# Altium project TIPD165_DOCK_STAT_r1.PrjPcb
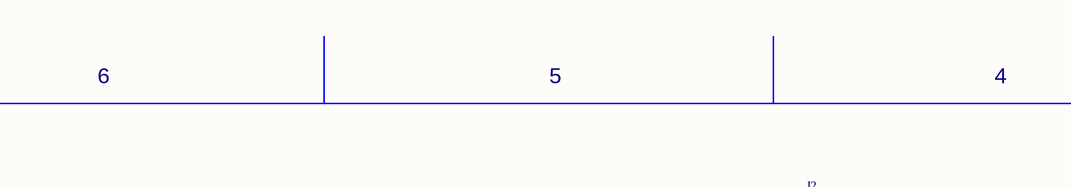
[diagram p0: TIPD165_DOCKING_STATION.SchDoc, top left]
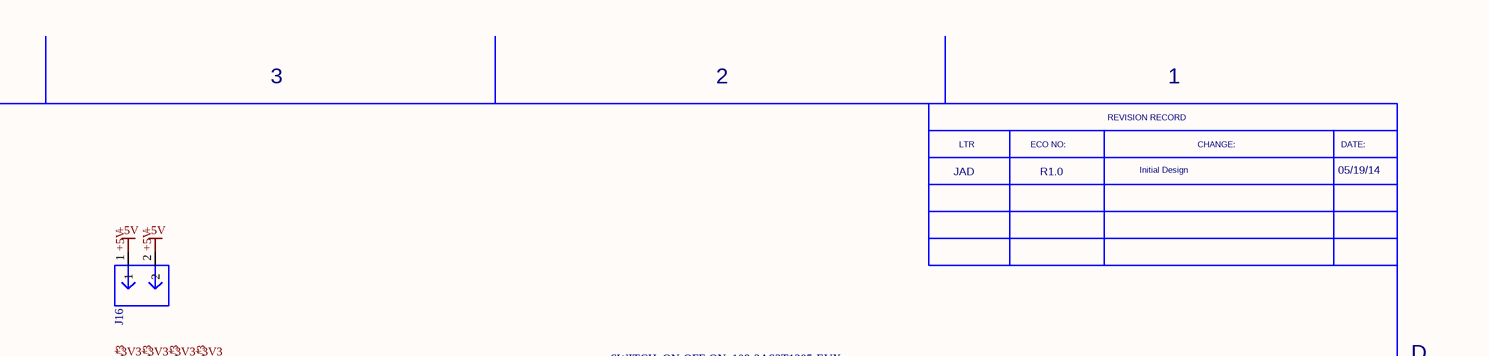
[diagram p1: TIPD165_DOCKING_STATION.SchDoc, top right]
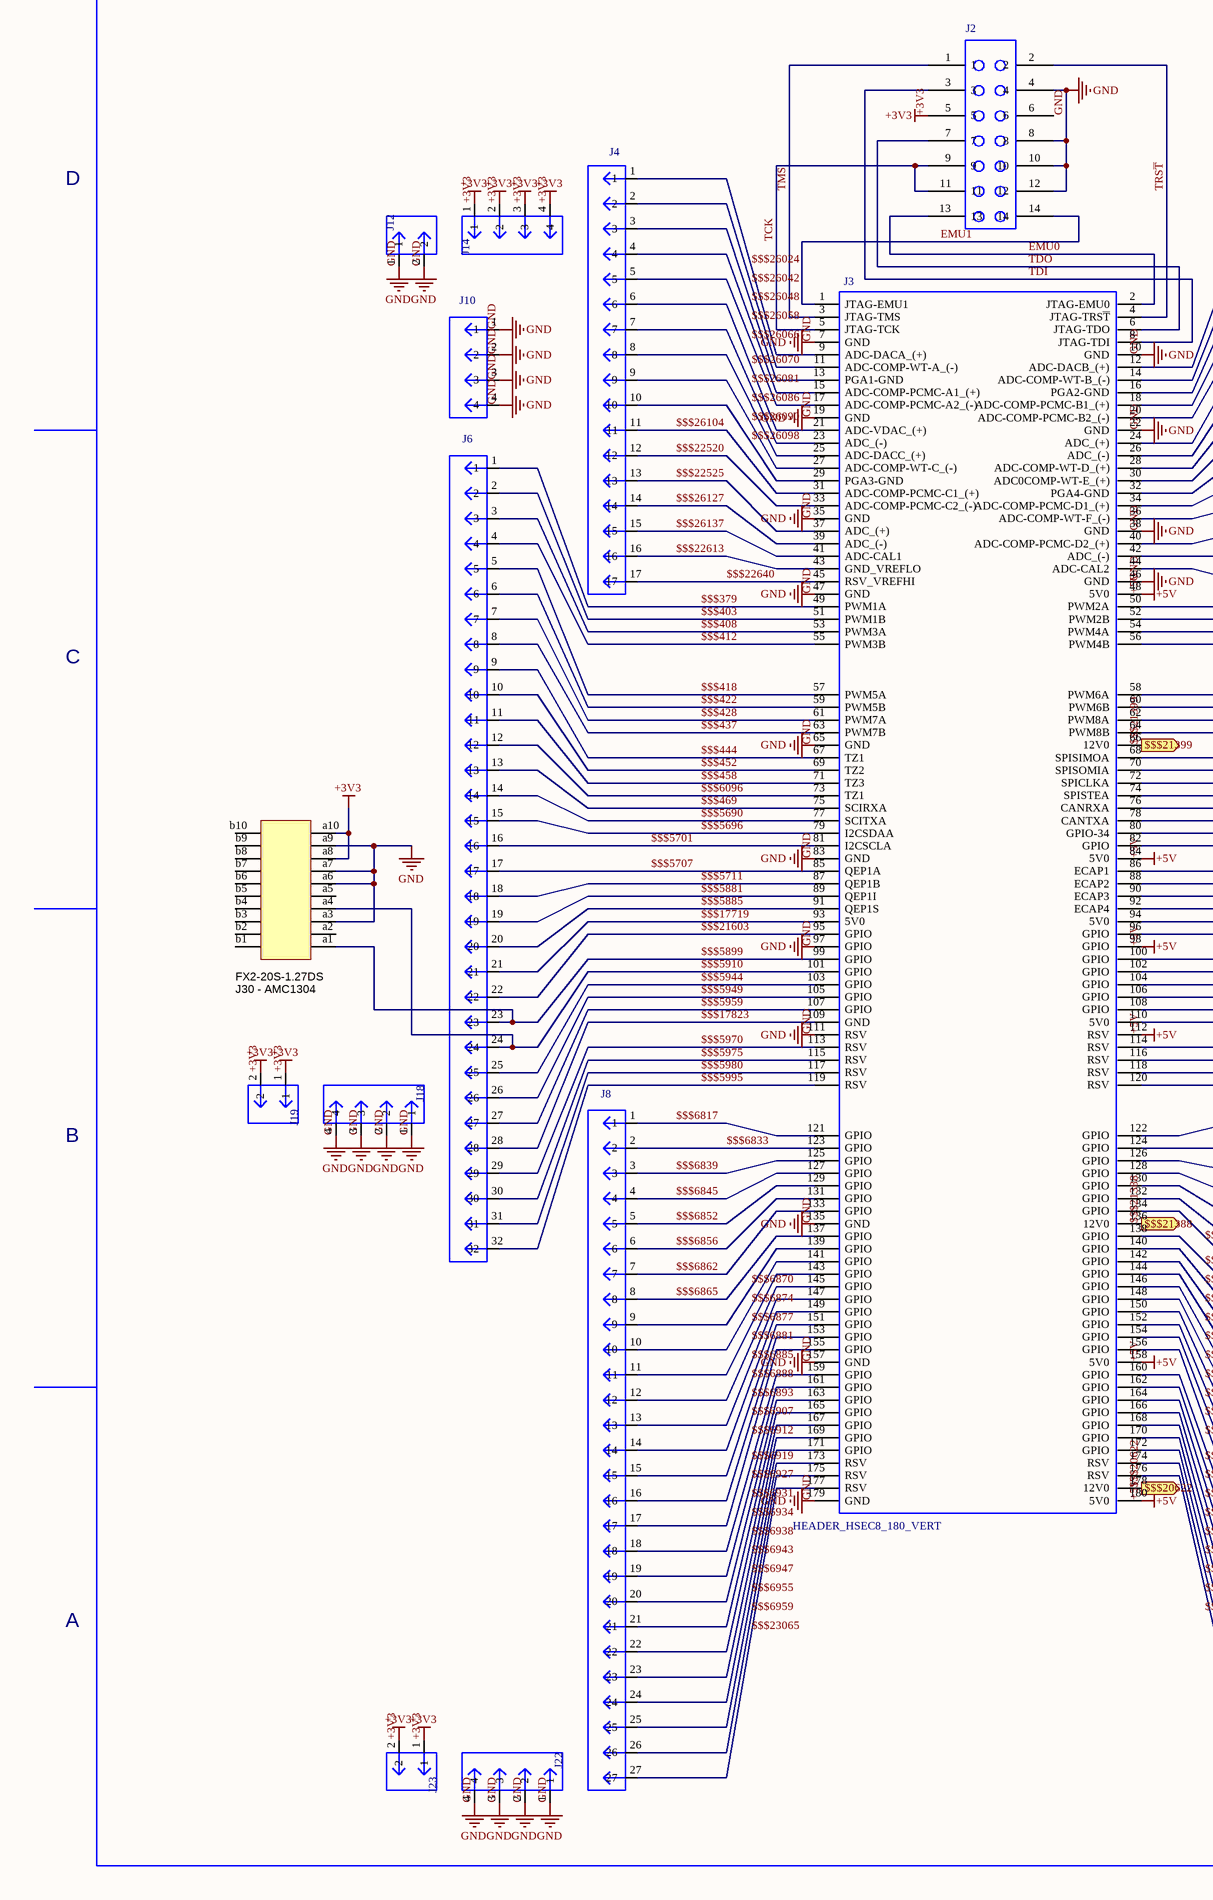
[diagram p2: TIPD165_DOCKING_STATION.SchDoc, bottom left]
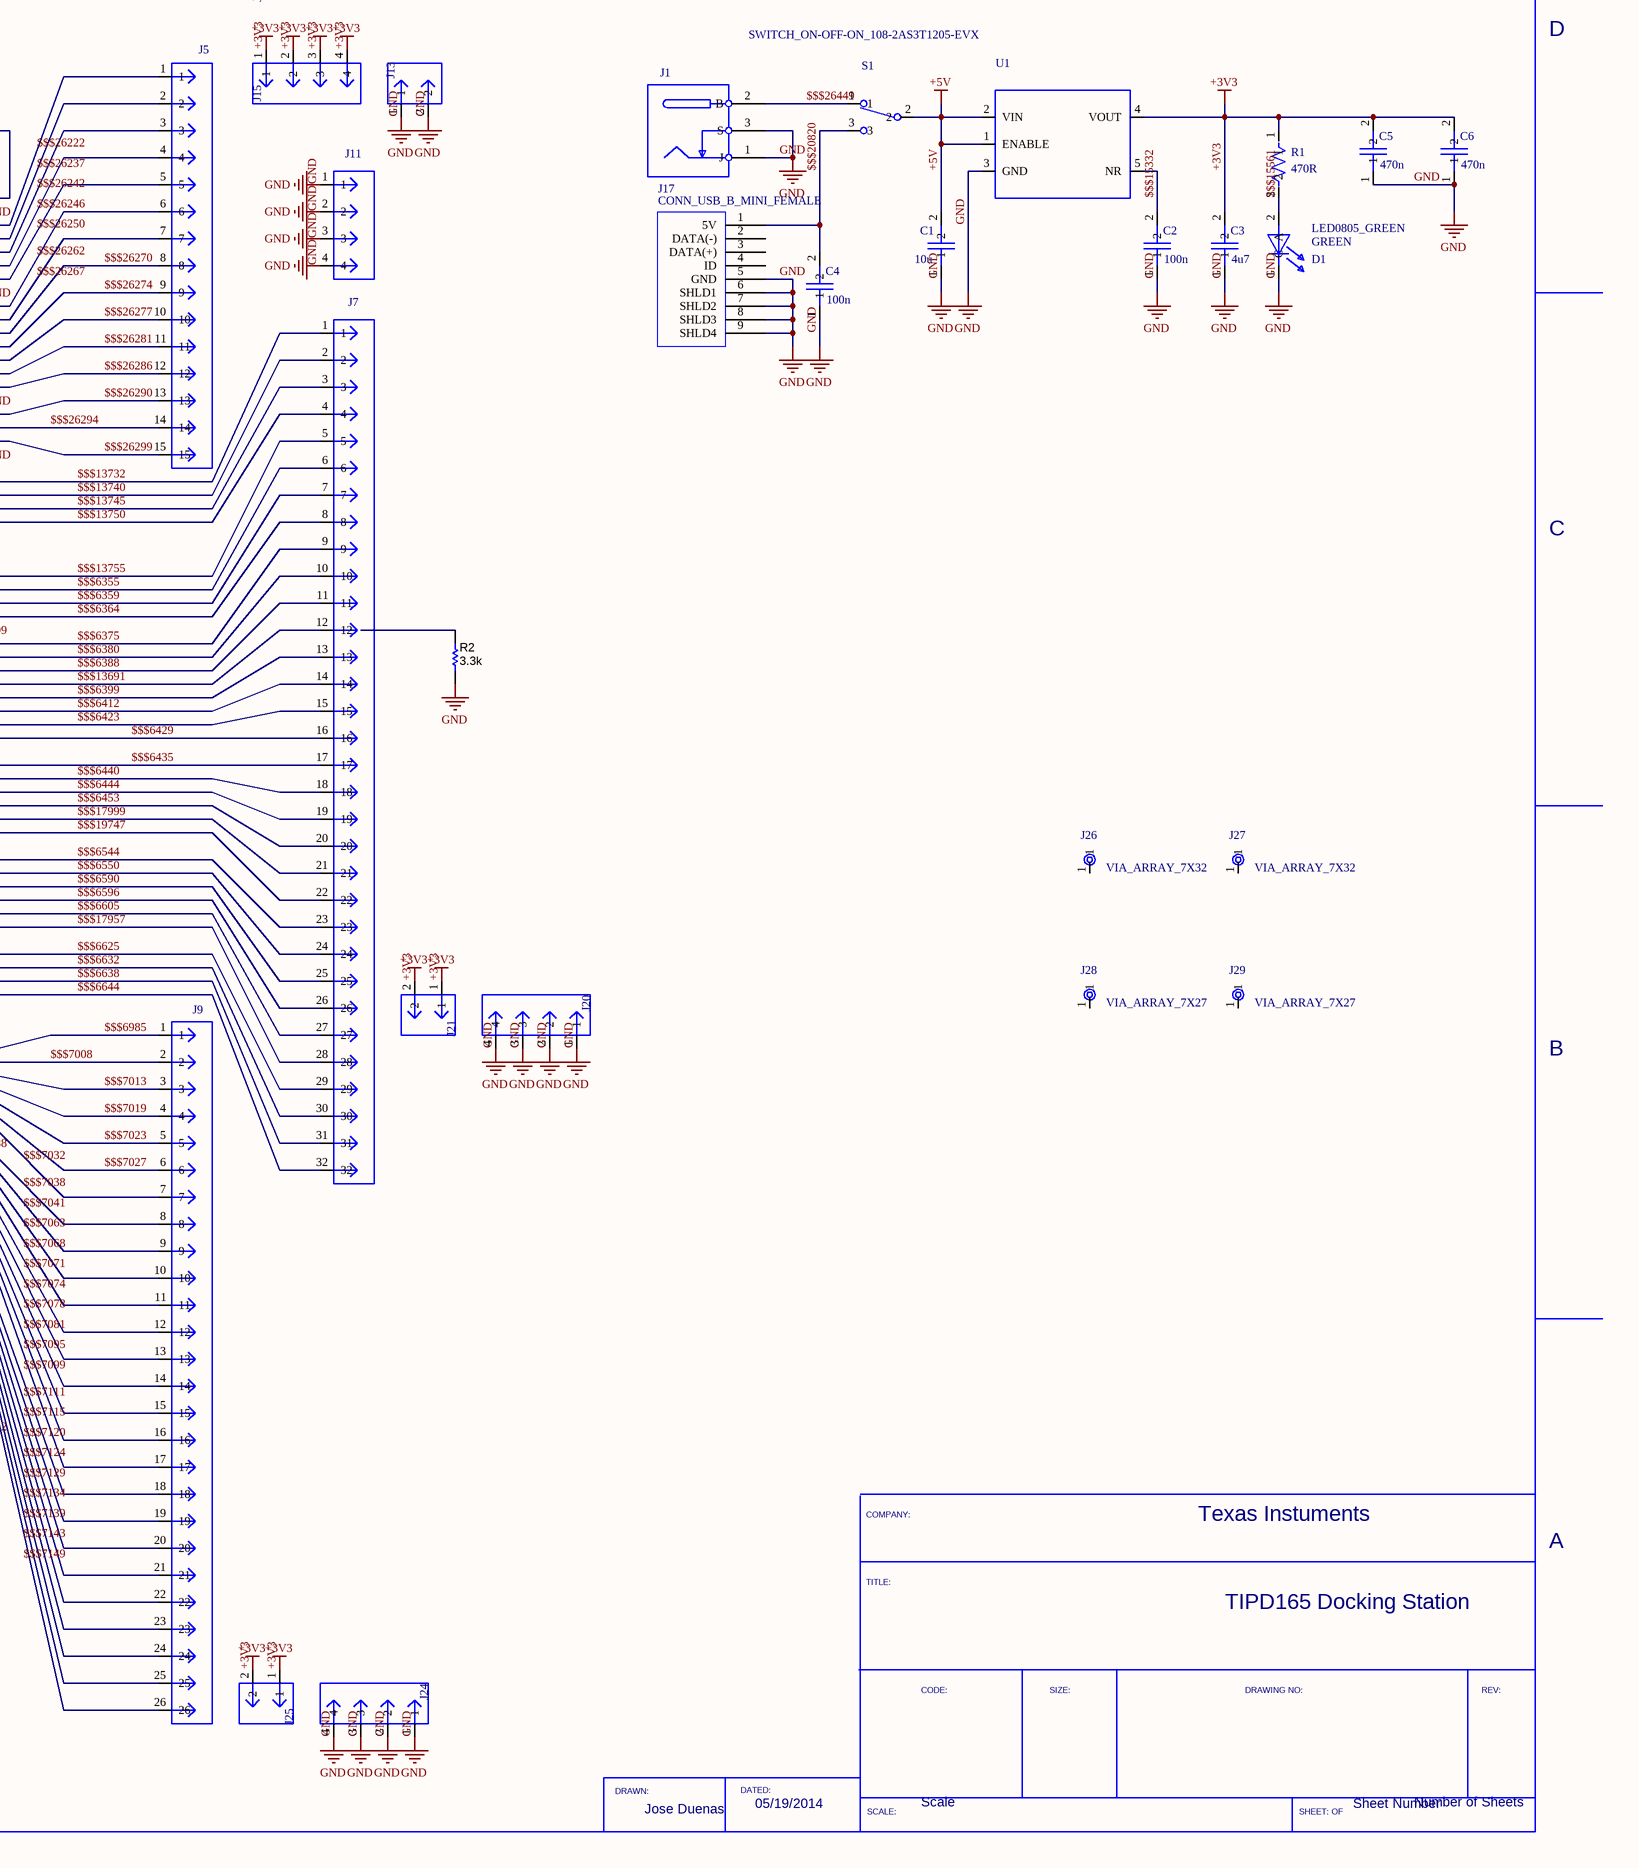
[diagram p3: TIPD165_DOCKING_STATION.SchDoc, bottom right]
1 sheet, 41 parts. Net scope: flat (ports and power ports of the same name join across sheets).
Board file: TIPD165_DOCK_STAT_r1.PcbDoc

## Sheet TIPD165_DOCKING_STATION.SchDoc: controlCARD Docking Station
size 558 x 431 mm; CompanyName: Texas Instruments Inc.; DrawnBy: SBL; Revision: 4.0; Drawn Date: 6/7/2012

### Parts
C1  value 10u  (hidden comment: C0805_6V3_X5R)
C2  value 100n  (hidden comment: C0805_6V3_X5R)
C3  value 4u7  (hidden comment: C0805_6V3_X5R)
C4  value 100n  (hidden comment: C0805_6V3_X5R)
C5  value 470n  (hidden comment: C0805_6V3_X5R)
C6  value 470n  (hidden comment: C0805_6V3_X5R)
D1  LED0805_GREEN  value GREEN
J1  CONN_PWR_JACK_2.5ID_5.5OD  (value not drawn)
J2  HEADER_7X2_100  (value not drawn)
J3  HEADER_HSEC8_180_VERT
J4  HEADER_1X17_100  (value not drawn)
J5  HEADER_1X15_100  (value not drawn)
J6  HEADER_1X32_100  (value not drawn)
J7  HEADER_1X32_100  (value not drawn)
J8  HEADER_1X27_100  (value not drawn)
J9  HEADER_1X26_100  (value not drawn)
J10  HEADER_1X4_100  (value not drawn)
J11  HEADER_1X4_100  (value not drawn)
J12  HEADER_1X2_100  (value not drawn)
J13  HEADER_1X2_100  (value not drawn)
J14  HEADER_1X4_100  (value not drawn)
J15  HEADER_1X4_100  (value not drawn)
J16  HEADER_1X2_100  (value not drawn)
J17  CONN_USB_B_MINI_FEMALE
J18  HEADER_1X4_100  (value not drawn)
J19  HEADER_1X2_100  (value not drawn)
J20  HEADER_1X4_100  (value not drawn)
J21  HEADER_1X2_100  (value not drawn)
J22  HEADER_1X4_100  (value not drawn)
J23  HEADER_1X2_100  (value not drawn)
J24  HEADER_1X4_100  (value not drawn)
J25  HEADER_1X2_100  (value not drawn)
J26  VIA_ARRAY_7X32
J27  VIA_ARRAY_7X32
J28  VIA_ARRAY_7X27
J29  VIA_ARRAY_7X27
J30_-_AMC1304  FX2-20S-1.27DS  [FX2_20P_1p27_DS_head_good]
R1  value 470R  (hidden comment: R0805_5%)
R2  ValueDisplayed: 3.3k  [0805_HV]  (hidden comment: ERJ-6GEYJ332V)
S1  SWITCH_ON-OFF-ON_108-2AS3T1205-EVX
U1  IC_LDO_TPS79533DCQ  (value not drawn)

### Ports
$$$20622, $$$21388, $$$21399

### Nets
+3V3: C3.2 C5.2 C6.2 J2.5 J14.1 J14.2 J14.3 J14.4 J15.1 J15.2 J15.3 J15.4 J19.1 J19.2 J21.1 J21.2 J23.1 J23.2 J25.1 J25.2 J30_-_AMC1304.a8 J30_-_AMC1304.a10 R1.1 U1.4(VOUT)
+5V: C1.2 J3.48(5V0) J3.84(5V0) J3.98(GPIO) J3.112(RSV) J3.158(5V0) J3.180(5V0) J16.1 J16.2 S1.2 U1.1(ENABLE) U1.2(VIN)
GND: C1.1 C2.1 C3.1 C4.1 C5.1 C6.1 D1.1(C) J1.1(J) J1.3(S) J2.4 J2.8 J2.10 J2.12 J3.7(GND) J3.10(GND) J3.19(GND) J3.22(GND) J3.35(GND) J3.38(GND) J3.46(GND) J3.47(GND) J3.65(GND) J3.83(GND) J3.97(GPIO) J3.111(RSV) J3.135(GND) J3.157(GND) J3.179(GND) J10.1 J10.2 J10.3 J10.4 J11.1 J11.2 J11.3 J11.4 J12.1 J12.2 J13.1 J13.2 J17.5(GND) J17.6(SHLD1) J17.7(SHLD2) J17.8(SHLD3) J17.9(SHLD4) J18.1 J18.2 J18.3 J18.4 J20.1 J20.2 J20.3 J20.4 J22.1 J22.2 J22.3 J22.4 J24.1 J24.2 J24.3 J24.4 J30_-_AMC1304.a3 J30_-_AMC1304.a6 J30_-_AMC1304.a7 J30_-_AMC1304.a9 R2.1 U1.3(GND) U1.6(GND)
$$$379: J3.49(PWM1A) J6.1
$$$403: J3.51(PWM1B) J6.2
$$$408: J3.53(PWM3A) J6.3
$$$412: J3.55(PWM3B) J6.4
$$$418: J3.57(PWM5A) J6.5
$$$422: J3.59(PWM5B) J6.6
$$$428: J3.61(PWM7A) J6.7
$$$437: J3.63(PWM7B) J6.8
$$$444: J3.67(TZ1) J6.9
$$$452: J3.69(TZ2) J6.10
$$$458: J3.71(TZ3) J6.11
$$$469: J3.75(SCIRXA) J6.13
$$$5690: J3.77(SCITXA) J6.14
$$$5696: J3.79(I2CSDAA) J6.15
$$$5701: J3.81(I2CSCLA) J6.16
$$$5707: J3.85(QEP1A) J6.17
$$$5711: J3.87(QEP1B) J6.18
$$$5881: J3.89(QEP1I) J6.19
$$$5885: J3.91(QEP1S) J6.20
$$$5899: J3.99(GPIO) J6.23 J30_-_AMC1304.a1
$$$5910: J3.101(GPIO) J6.24 J30_-_AMC1304.a4
$$$5944: J3.103(GPIO) J6.25
$$$5949: J3.105(GPIO) J6.26
$$$5959: J3.107(GPIO) J6.27
$$$5970: J3.113(RSV) J6.29
$$$5975: J3.115(RSV) J6.30
$$$5980: J3.117(RSV) J6.31
$$$5995: J3.119(RSV) J6.32
$$$6096: J3.73(TZ1) J6.12
$$$6355: J3.60(PWM6B) J7.6
$$$6359: J3.62(PWM8A) J7.7
$$$6364: J3.64(PWM8B) J7.8
$$$6375: J3.68(SPISIMOA) J7.9
$$$6380: J3.70(SPISOMIA) J7.10
$$$6388: J3.72(SPICLKA) J7.11
$$$6399: J3.76(CANRXA) J7.13
$$$6412: J3.78(CANTXA) J7.14
$$$6423: J3.80(GPIO-34) J7.15
$$$6429: J3.82(GPIO) J7.16
$$$6435: J3.86(ECAP1) J7.17
$$$6440: J3.88(ECAP2) J7.18
$$$6444: J3.90(ECAP3) J7.19
$$$6453: J3.92(ECAP4) J7.20
$$$6544: J3.100(GPIO) J7.23
$$$6550: J3.102(GPIO) J7.24
$$$6590: J3.104(GPIO) J7.25
$$$6596: J3.106(GPIO) J7.26
$$$6605: J3.108(GPIO) J7.27
$$$6625: J3.114(RSV) J7.29
$$$6632: J3.116(RSV) J7.30
$$$6638: J3.118(RSV) J7.31
$$$6644: J3.120(RSV) J7.32
$$$6817: J3.121(GPIO) J8.1
$$$6833: J3.123(GPIO) J8.2
$$$6839: J3.125(GPIO) J8.3
$$$6845: J3.127(GPIO) J8.4
$$$6852: J3.129(GPIO) J8.5
$$$6856: J3.131(GPIO) J8.6
$$$6862: J3.133(GPIO) J8.7
$$$6865: J3.137(GPIO) J8.8
$$$6870: J3.139(GPIO) J8.9
$$$6874: J3.141(GPIO) J8.10
$$$6877: J3.143(GPIO) J8.11
$$$6881: J3.145(GPIO) J8.12
$$$6885: J3.147(GPIO) J8.13
$$$6888: J3.149(GPIO) J8.14
$$$6893: J3.151(GPIO) J8.15
$$$6907: J3.153(GPIO) J8.16
$$$6912: J3.155(GPIO) J8.17
$$$6919: J3.159(GPIO) J8.18
$$$6927: J3.161(GPIO) J8.19
$$$6931: J3.163(GPIO) J8.20
$$$6934: J3.165(GPIO) J8.21
$$$6938: J3.167(GPIO) J8.22
$$$6943: J3.169(GPIO) J8.23
$$$6947: J3.171(GPIO) J8.24
$$$6955: J3.173(RSV) J8.25
$$$6959: J3.175(RSV) J8.26
$$$6985: J3.122(GPIO) J9.1
$$$7008: J3.124(GPIO) J9.2
$$$7013: J3.126(GPIO) J9.3
$$$7019: J3.128(GPIO) J9.4
$$$7023: J3.130(GPIO) J9.5
$$$7027: J3.132(GPIO) J9.6
$$$7095: J3.156(GPIO) J9.17
$$$7111: J3.162(GPIO) J9.19
$$$7115: J3.164(GPIO) J9.20
$$$13691: J3.74(SPISTEA) J7.12
$$$13732: J3.50(PWM2A) J7.1
$$$13740: J3.52(PWM2B) J7.2
$$$13745: J3.54(PWM4A) J7.3
$$$13750: J3.56(PWM4B) J7.4
$$$13755: J3.58(PWM6A) J7.5
$$$15332: C2.2 U1.5(NR)
$$$15561: D1.2(A) R1.2
$$$17719: J3.93(5V0) J6.21
$$$17823: J3.109(GND) J6.28
$$$17957: J3.110(5V0) J7.28
$$$17999: J3.94(5V0) J7.21
$$$19747: J3.96(GPIO) J7.22
$$$20622: J3.178(12V0) ; port $$$20622
$$$20820: C4.2 J17.1(5V) S1.3
$$$21388: J3.136(12V0) ; port $$$21388
$$$21399: J3.66(12V0) ; port $$$21399
$$$21603: J3.95(GPIO) J6.22
$$$22520: J3.33(ADC-COMP-PCMC-C2_(-)) J4.12
$$$22525: J3.37(ADC_(+)) J4.13
$$$22613: J3.43(GND_VREFLO) J4.16
$$$22640: J3.45(RSV_VREFHI) J4.17
$$$23065: J3.177(RSV) J8.27
$$$26024: J3.9(ADC-DACA_(+)) J4.1
$$$26042: J3.11(ADC-COMP-WT-A_(-)) J4.2
$$$26048: J3.13(PGA1-GND) J4.3
$$$26058: J3.15(ADC-COMP-PCMC-A1_(+)) J4.4
$$$26066: J3.17(ADC-COMP-PCMC-A2_(-)) J4.5
$$$26070: J3.21(ADC-VDAC_(+)) J4.6
$$$26081: J3.23(ADC_(-)) J4.7
$$$26086: J3.25(ADC-DACC_(+)) J4.8
$$$26090: J3.27(ADC-COMP-WT-C_(-)) J4.9
$$$26098: J3.29(PGA3-GND) J4.10
$$$26104: J3.31(ADC-COMP-PCMC-C1_(+)) J4.11
$$$26127: J3.39(ADC_(-)) J4.14
$$$26137: J3.41(ADC-CAL1) J4.15
$$$26222: J3.12(ADC-DACB_(+)) J5.1
$$$26237: J3.14(ADC-COMP-WT-B_(-)) J5.2
$$$26242: J3.16(PGA2-GND) J5.3
$$$26246: J3.18(ADC-COMP-PCMC-B1_(+)) J5.4
$$$26250: J3.20(ADC-COMP-PCMC-B2_(-)) J5.5
$$$26262: J3.24(ADC_(+)) J5.6
$$$26267: J3.26(ADC_(-)) J5.7
$$$26270: J3.28(ADC-COMP-WT-D_(+)) J5.8
$$$26274: J3.30(ADC0COMP-WT-E_(+)) J5.9
$$$26277: J3.32(PGA4-GND) J5.10
$$$26281: J3.34(ADC-COMP-PCMC-D1_(+)) J5.11
$$$26286: J3.36(ADC-COMP-WT-F_(-)) J5.12
$$$26290: J3.40(ADC-COMP-PCMC-D2_(+)) J5.13
$$$26294: J3.42(ADC_(-)) J5.14
$$$26299: J3.44(ADC-CAL2) J5.15
$$$26449: J1.2(B) S1.1
TRS~{T}: J2.2 J3.4(JTAG-TRS~{T})
EMU0: J2.13 J3.2(JTAG-EMU0)
EMU1: J2.14 J3.1(JTAG-EMU1)
TCK: J2.9 J2.11 J3.5(JTAG-TCK)
TDI: J2.3 J3.8(JTAG-TDI)
TDO: J2.7 J3.6(JTAG-TDO)
TMS: J2.1 J3.3(JTAG-TMS)
NetJ3_134: J3.134(GPIO) J9.7
NetJ3_138: J3.138(GPIO) J9.8
NetJ3_140: J3.140(GPIO) J9.9
NetJ3_142: J3.142(GPIO) J9.10
NetJ3_144: J3.144(GPIO) J9.11
NetJ3_146: J3.146(GPIO) J9.12
NetJ3_148: J3.148(GPIO) J9.13
NetJ3_150: J3.150(GPIO) J9.14
NetJ3_152: J3.152(GPIO) J9.15
NetJ3_154: J3.154(GPIO) J9.16
NetJ3_160: J3.160(GPIO) J9.18
NetJ3_166: J3.166(GPIO) J9.21
NetJ3_168: J3.168(GPIO) J9.22
NetJ3_170: J3.170(GPIO) J9.23
NetJ3_172: J3.172(GPIO) J9.24
NetJ3_174: J3.174(RSV) J9.25
NetJ3_176: J3.176(RSV) J9.26

Not connected (* = marked no-connect by the designer): J2 6; J17 2(DATA(-)) 3(DATA(+)) 4(ID); J26 1; J27 1; J28 1; J29 1; J30_-_AMC1304 a2 a5 b1 b2 b3 b4 b5 b6 b7 b8 b9 b10; R2 2

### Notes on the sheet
- 6
- 5
- 4
- 3
- 2
- 1
- LTR
- ECO NO:
- REVISION RECORD
- CHANGE:
- DATE:
- JAD
- R1.0
- Initial Design
- 05/19/14
- D
- C
- B
- COMPANY:
- Texas Instuments
- A
- TITLE:
- TIPD165 Docking Station
- CODE:
- SIZE:
- DRAWING NO:
- REV:
- DRAWN:
- DATED:
- Jose Duenas
- 05/19/2014
- SCALE:
- Scale
- SHEET: OF
- Sheet Number
- Number of Sheets
- Labels drawn without touching a wire or pin: $$$7032, $$$7038, $$$7041, $$$7063, $$$7068, $$$7071, $$$7074, $$$7078, $$$7081, $$$7099, $$$7120, $$$7124, $$$7129, $$$7134, $$$7139, $$$7143, $$$7149

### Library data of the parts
C1-C6 = C0805_6V3_X5R: CAP CER 6V3 10% X5R 0805; Decal: C0805
D1 = LED0805_GREEN: LED GREEN 0805 SMD, Diffused, 567nm
J1 = CONN_PWR_JACK_2.5ID_5.5OD: CONN PWR JACK 2.5X5.5MM HIGH CUR; Part Number: PJ-002BH; Decal: CONN_PWR_JACK_2.1ID_5.5OD
J2 = HEADER_7X2_100: Header, Male, 7x2-pin, 100mil spacing
J3 = HEADER_HSEC8_180_VERT: 180 pin (120 + 60) HSEC8 socket, samtec; Part Number: HSEC8-130-01-L-DV-A & HSEC8-160-01-L-DV-A-BL; Decal: HEADER_HSEC8_180_DV; Value: HSEC8 180pin
J4 = HEADER_1X17_100: Header, Male, 1x17-pin, 100mil spacing
J5 = HEADER_1X15_100: Header, Male, 1x15-pin, 100mil spacing
J6 J7 = HEADER_1X32_100: Header, Male, 1x32-pin, 100mil spacing
J8 = HEADER_1X27_100: Header, Male, 1x27-pin, 100mil spacing
J9 = HEADER_1X26_100: Header, Male, 1x26-pin, 100mil spacing
J10 J11 J14 J15 J18 J20 J22 J24 = HEADER_1X4_100: Header, Male, 1x4-pin, 100mil spacing
J12 J13 J16 J19 J21 J23 J25 = HEADER_1X2_100: Header, Male, 1x2-pin, 100mil spacing
J17 = CONN_USB_B_MINI_FEMALE: CONN RECEPT MINI USB2.0 5POS; Part Number: UX60-MB-5ST
J26 J27 = VIA_ARRAY_7X32: PCB DECAL: VIA_ARRAY_7X32_100
J28 J29 = VIA_ARRAY_7X27: PCB DECAL: VIA_ARRAY_7X27_100
J30_-_AMC1304 = FX2_20P_1p27_DS_head_compon: 1.27mm Pitch Multi-function Two Piece Connector; Manufacturer: Hirose; SymbolCreator: Use a-id; U/M: EA, IN, or GM
R1 = R0805_5%: RES 1/8W 5% 0805 SMD; Decal: R0805
R2 = ERJ-6GEYJ332V: RES, 3.3 k, 5%, 0.125 W, 0805; Manufacturer: Panasonic; CompType: Resistor; Value: 3.3k; Res_ohm: 3300; Value_Code: 3k30; Tolerance_%: 5; Power_W: 0.125; Value2: 0.125W; VDC_V: 150; TempCo: 200 ppm/C; EIA_Code: E24; U/M: EA
S1 = SWITCH_ON-OFF-ON_108-2AS3T1205-EVX: Toggle Switches SPDT ON-ON PC MOUNT; Part Number: 108-2AS1T1203-EVX; Decal: SWITCH_108-2AS1T1203-EVX; PCB DECAL: SWITCH_108-2AS3T1205-EVX
U1 = IC_LDO_TPS79533DCQ: IC LDO REG 3.3V 500MA SOT223-6; Decal: SOT-223-6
